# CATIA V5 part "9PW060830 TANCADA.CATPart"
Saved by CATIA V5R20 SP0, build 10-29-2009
Part number: 9PW060830 TANCADA
Revision: ANY
Definition: UNKNOWN
Nomenclature: 9PW060830 TANCADA
Source: Unknown
Bounding box of the stored display mesh (mm): x -175 to 0, y -6.5 to 3.5, z -4.1 to 4.1
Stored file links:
  C:\Users\Utente\Desktop\IO LAVORO\3D X SITO CF\CUMSA\3D files PW\pw060830\pw060830_injection\9PW060830 TANCADA.CATPart
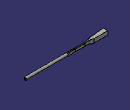
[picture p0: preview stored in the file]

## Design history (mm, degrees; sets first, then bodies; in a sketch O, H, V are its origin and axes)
Body1 "Chaflán1" (main body)
  Solid1: solid without history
